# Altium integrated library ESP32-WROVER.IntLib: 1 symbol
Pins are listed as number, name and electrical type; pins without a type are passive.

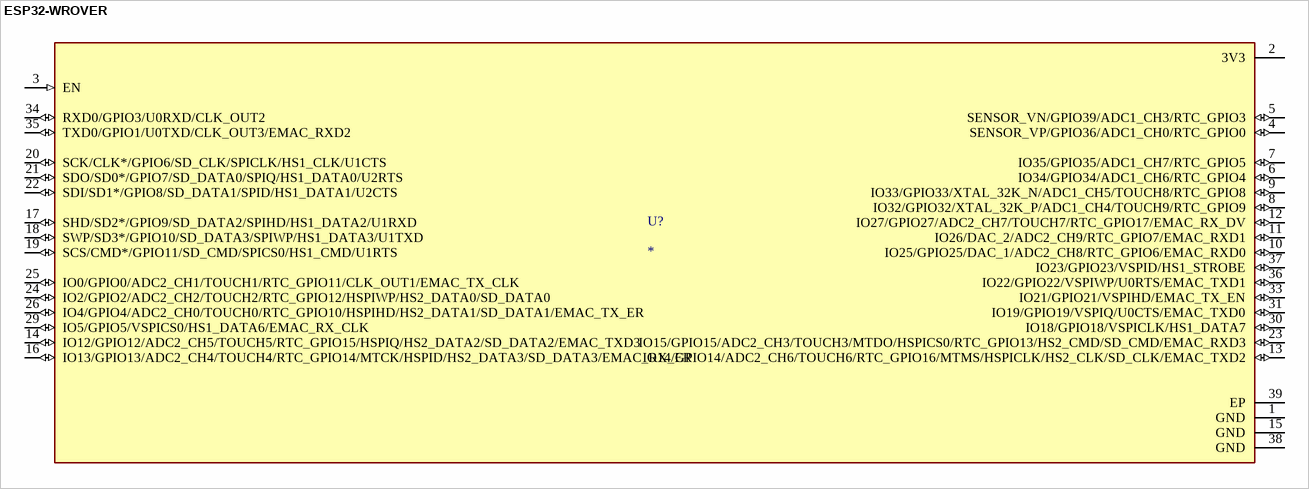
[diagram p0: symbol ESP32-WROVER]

## ESP32-WROVER
designator U?
Module: combo; GPIO, I2C x2, I2S x2, SDIO, SPI x3, UART x3; 19.5dBm; MP: ESP32-WROVER
footprint XCVR_ESP32-WROVER
pins: 1 GND (power), 2 3V3 (power), 3 EN (in), 4 SENSOR_VP/GPIO36/ADC1_CH0/RTC_GPIO0 (io), 5 SENSOR_VN/GPIO39/ADC1_CH3/RTC_GPIO3 (io), 6 IO34/GPIO34/ADC1_CH6/RTC_GPIO4 (io), 7 IO35/GPIO35/ADC1_CH7/RTC_GPIO5 (io), 8 IO32/GPIO32/XTAL_32K_P/ADC1_CH4/TOUCH9/RTC_GPIO9 (io), 9 IO33/GPIO33/XTAL_32K_N/ADC1_CH5/TOUCH8/RTC_GPIO8 (io), 10 IO25/GPIO25/DAC_1/ADC2_CH8/RTC_GPIO6/EMAC_RXD0 (io), 11 IO26/DAC_2/ADC2_CH9/RTC_GPIO7/EMAC_RXD1 (io), 12 IO27/GPIO27/ADC2_CH7/TOUCH7/RTC_GPIO17/EMAC_RX_DV (io), 13 IO14/GPIO14/ADC2_CH6/TOUCH6/RTC_GPIO16/MTMS/HSPICLK/HS2_CLK/SD_CLK/EMAC_TXD2 (io), 14 IO12/GPIO12/ADC2_CH5/TOUCH5/RTC_GPIO15/HSPIQ/HS2_DATA2/SD_DATA2/EMAC_TXD3 (io), 15 GND (power), 16 IO13/GPIO13/ADC2_CH4/TOUCH4/RTC_GPIO14/MTCK/HSPID/HS2_DATA3/SD_DATA3/EMAC_RX_ER (io), 17 SHD/SD2*/GPIO9/SD_DATA2/SPIHD/HS1_DATA2/U1RXD (io), 18 SWP/SD3*/GPIO10/SD_DATA3/SPIWP/HS1_DATA3/U1TXD (io), 19 SCS/CMD*/GPIO11/SD_CMD/SPICS0/HS1_CMD/U1RTS (io), 20 SCK/CLK*/GPIO6/SD_CLK/SPICLK/HS1_CLK/U1CTS (io), 21 SDO/SD0*/GPIO7/SD_DATA0/SPIQ/HS1_DATA0/U2RTS (io), 22 SDI/SD1*/GPIO8/SD_DATA1/SPID/HS1_DATA1/U2CTS (io), 23 IO15/GPIO15/ADC2_CH3/TOUCH3/MTDO/HSPICS0/RTC_GPIO13/HS2_CMD/SD_CMD/EMAC_RXD3 (io), 24 IO2/GPIO2/ADC2_CH2/TOUCH2/RTC_GPIO12/HSPIWP/HS2_DATA0/SD_DATA0 (io), 25 IO0/GPIO0/ADC2_CH1/TOUCH1/RTC_GPIO11/CLK_OUT1/EMAC_TX_CLK (io), 26 IO4/GPIO4/ADC2_CH0/TOUCH0/RTC_GPIO10/HSPIHD/HS2_DATA1/SD_DATA1/EMAC_TX_ER (io), 29 IO5/GPIO5/VSPICS0/HS1_DATA6/EMAC_RX_CLK (io), 30 IO18/GPIO18/VSPICLK/HS1_DATA7 (io), 31 IO19/GPIO19/VSPIQ/U0CTS/EMAC_TXD0 (io), 33 IO21/GPIO21/VSPIHD/EMAC_TX_EN (io), 34 RXD0/GPIO3/U0RXD/CLK_OUT2 (io), 35 TXD0/GPIO1/U0TXD/CLK_OUT3/EMAC_RXD2 (io), 36 IO22/GPIO22/VSPIWP/U0RTS/EMAC_TXD1 (io), 37 IO23/GPIO23/VSPID/HS1_STROBE (io), 38 GND (power), 39 EP (power)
